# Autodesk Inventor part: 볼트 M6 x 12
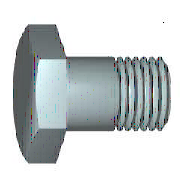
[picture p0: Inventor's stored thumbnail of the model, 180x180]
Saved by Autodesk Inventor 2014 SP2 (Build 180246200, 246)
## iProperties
Created: 2012-02
Part Number: 볼트 M6 x 12
Material: 스테인리스강
Description: 6각 머리 나사. 제품 등급 C
Document SubType Name: Modeling
Standard: ISO 4018
Designer: mduedu
Standard Revision: Third edition 1999-08-15
Standards Organization: ISO
Language: ko-KR
Size Designation: M6 x 12
Categories: <MemberInstance><Categories><Category DisplayName="조임쇠" InternalName="e4da775c-781d-43d5-af7c-5136215cf5a6" Mnemonic="FSTN"><Category DisplayName="볼트" InternalN
Density: 8.08 g/cm^3
Appearance: 반광택
IsCustomPart: 0
Author: mduedu
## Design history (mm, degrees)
node "WorkPlane1"
node "WorkPoint1"
node "MSC_A1"
node "MSC_PF1"
node "MSC_PT1"
body "Solid1"
node "스케치1"
sketch "스케치2"
  geometry: L1 (-5, 2.887)-(-5, -2.887); L2 (0, 5.773)-(-5, 2.887); L3 (5, 2.887)-(0, 5.773); L4 (5, -2.887)-(5, 2.887); L5 (0, -5.773)-(5, -2.887); L6 (-5, -2.887)-(0, -5.773); C1 r 5 at (0, 0); 1 further point
  constraints: 12 end point, 6 tangent, 2 parallel, 2 vertical, 1 centre point
  dimensions: "d1" = 10 diameter of C1 (= ParS); "d29" = 0 distance of point (0, 0) C1.centre; "d30" = 0 distance of C1.centre point (0, 0)
extrude "돌출1" new body sketch "스케치2" distance "d6" = 4 (= ParK); taper "d7" = 0 deg
revolve "회전1" stored, may be unused: angle "d14" = 360 deg
revolve "회전2" stored, may be unused: angle "d21" = 360 deg
chamfer "모따기1" distance "d22" = 0.5 (= 0.5 x PTC); stored, may be unused: second distance "d23" = 0.5 (= 0.5 x PTC), angle "d39" = 45 deg
fillet "모깎기1" dims "d24" = 0.25 (= r)
feature "스레드1" dims "d32" = 0, "b" = 10 (= NLG - 2 x PTC)
sketch "스케치3"
  geometry: L1 (5, 4)-(5.873, 4); L2 (5.873, 3.496)-(5, 4); L3 (5.873, 4)-(5.873, 3.496); L4 (0, -0.8)-(0, 4.8) reference; L5 (5.773, 0)-(5.773, 4) reference
  constraints: 6 end point, 1 horizontal, 1 vertical
  dimensions: "d25" = 0.1 distance between parallel lines of L5 L3; "d26" = 0 distance from line of L5.end L1; "d27" = 60 deg angle of L3 L2; "d28" = 5 distance from line of L4 L1.start (= 0.5 x ParS)
sketch "스케치4"
  geometry: L1 (0, -12)-(0, 0); L2 (-3, -12)-(0, -12); L3 (-3, 0)-(-3, -12); L4 (0, 0)-(-3, 0); L5 (0, -12)-(0, 0); L6 (-3.6, 0)-(0.6, 0) reference; L7 (0, -14.4)-(0, 2.4) reference
  constraints: 10 end point, 2 horizontal, 2 vertical
  dimensions: "d18" = 3 distance of L1.start L2.start (= 0.5 x NND); "d20" = 12 distance of L3.start L2.start (= NLG); "d33" = 0 distance between parallel lines of L7 L1; "d34" = 0 distance between parallel lines of L6 L4
other parameters: "NND" = 6 [user parameter; used in 2 equation terms], "NLG" = 12 [user parameter; used in 2 equation terms], "PTC" = 1 [user parameter; used in 3 equation terms], "ParK" = 4 [user parameter; used in 1 equation term], "ParS" = 10 [user parameter; used in 3 equation terms], "msp_es" = 5.77367 (= 0.577367 x ParS) [user parameter], "r" = 0.25 [user parameter; used in 1 equation term], "d2" = 15 (derived), "d4" = 17.32102 (derived), "d8" = 15 (derived), "d10" = 0 (derived), "d12" = 30 deg (derived), "d15" = 0 (derived), "d37" = 0, "d38" = 0, "d40" = 0, "d41" = 0, "d42" = 0, "THREADDIA" = 6 (= NND) [user parameter]
